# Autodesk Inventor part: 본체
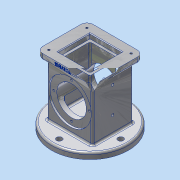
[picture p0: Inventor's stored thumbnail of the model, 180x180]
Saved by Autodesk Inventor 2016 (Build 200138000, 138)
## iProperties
Created: 2018-10
Part Number: 본체
Material: 알루미늄 6061
Document SubType Name: Modeling
Designer: MIRAE
Density: 2.7 g/cm^3
Appearance: 알루미늄 - 평지
Mass: 984.574 g
Surface Area: 743.905 cm^2
Volume: 364.657 cm^3
Author: MIRAE
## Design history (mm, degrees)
sketch "스케치1"
  geometry: C1 r 62.5 at (0, 0); 1 further point
  constraints: 1 centre point, 1 coincident
  dimensions: "d0" = 125 diameter of C1
extrude "돌출1" new body sketch "스케치1" distance "d1" = 10; taper "d2" = 0 deg
sketch "스케치2"
  geometry: L1 (37, 33)-(-37, 33); L2 (-37, 33)-(-37, -33); L3 (-37, -33)-(37, -33); L4 (37, -33)-(37, 33); L5 (37, 33)-(-37, -33); L6 (-37, 33)-(37, -33); 1 further point
  constraints: 12 end point, 2 midpoint, 2 parallel, 1 horizontal, 1 perpendicular
  dimensions: "d3" = 74 distance of L1.start L1.end; "d4" = 66 distance of L3.end L1.start
extrude "돌출2" join sketch "스케치2" distance "d5" = 88; taper "d6" = 0 deg
sketch "스케치3"
  geometry: L1 (46, 41)-(-46, 41); L2 (-46, 41)-(-46, -41); L3 (-46, -41)-(46, -41); L4 (46, -41)-(46, 41); L5 (46, 41)-(-46, -41); L6 (-46, 41)-(46, -41); 1 further point
  constraints: 12 end point, 2 midpoint, 2 parallel, 1 horizontal, 1 perpendicular
  dimensions: "d7" = 92 distance of L1.start L1.end; "d8" = 82 distance of L3.end L1.start
extrude "돌출3" join sketch "스케치3" distance "d9" = 10; taper "d10" = 0 deg
sketch "스케치4"
  geometry: L1 (22, 22)-(-22, 22); L2 (-22, 22)-(-22, -22); L3 (-22, -22)-(22, -22); L4 (22, -22)-(22, 22); L5 (22, 22)-(-22, -22); L6 (-22, 22)-(22, -22); 1 further point
  constraints: 12 end point, 2 midpoint, 2 parallel, 1 horizontal, 1 perpendicular
  dimensions: "d11" = 44 distance of L2.end L3.end; "d12" = 44 distance of L3.end L1.start
extrude "돌출4" cut sketch "스케치4" distance "d13" = 82; taper "d14" = 0 deg
sketch "스케치5"
  geometry: L1 (26, 26)-(-26, 26); L2 (-26, 26)-(-26, -26); L3 (-26, -26)-(26, -26); L4 (26, -26)-(26, 26); L5 (26, 26)-(-26, -26); L6 (-26, 26)-(26, -26); 1 further point
  constraints: 12 end point, 2 midpoint, 2 parallel, 1 horizontal, 1 perpendicular
  dimensions: "d15" = 52 distance of L2.end L3.end; "d16" = 52 distance of L3.end L1.start
extrude "돌출5" cut sketch "스케치5" distance "d17" = 8; taper "d18" = 0 deg
sketch "스케치6"
  geometry: L1 (-25.5, -10)-(99.5, -10) reference; C1 r 24 at (37, 44); 1 further point
  constraints: 1 centre point, 1 vertical alignment
  dimensions: "d19" = 48 diameter of C1; "d20" = 54 distance from line of L1 C1.centre
extrude "돌출6" cut sketch "스케치6" stored distance "d21" = 8; taper "d22" = 0 deg
sketch "스케치7"
  geometry: C1 r 24 at (37, 44) reference; C2 r 35 at (37, 44); 1 further point
  constraints: 1 centre point, 1 coincident
  dimensions: "d23" = 70 diameter of C2
extrude "돌출7" cut sketch "스케치7" distance "d24" = 3; taper "d25" = 0 deg
sketch "스케치8"
  geometry: L1 (15, -16)-(59, -16) reference; C1 r 24 at (37, -44) reference; C2 r 35 at (37, -44); 1 further point
  constraints: 1 centre point, 1 coincident
  dimensions: "d26" = 70 diameter of C2
extrude "돌출8" cut sketch "스케치8" distance "d27" = 3; taper "d28" = 0 deg
sketch "스케치9"
  geometry: 2 further points
  constraints: 1 vertical alignment
  dimensions: "d29" = 50 distance of point (0, 0) point (0, 50)
hole "구멍1" sketch "스케치9" at (0, 50) diameter "d30" = 9; stored, may be unused: countersink angle "d34" = 90 deg, drill point angle "d36" = 118 deg; dims "d31" = 6, "d32" = 4, "d33" = 2, "d35" = 8
sketch "스케치10"
  geometry: C1 r 24 at (0, 0) reference; 2 further points
  constraints: 1 vertical alignment
  dimensions: "d40" = 29 distance of C1.centre point (0, 29)
hole "구멍2" sketch "스케치10" at (0, 29) diameter "d41" = 3.242; stored, may be unused: countersink angle "d45" = 90 deg, drill point angle "d47" = 118 deg; dims "d42" = 4, "d43" = 4, "d44" = 2, "d46" = 6
sketch "스케치11"
  geometry: L1 (10, -29.5)-(10, 95.5) reference; 2 further points
  constraints: 1 horizontal alignment
  dimensions: "d51" = 37 distance from line of point (-27, 33) L1
hole "구멍3" sketch "스케치11" at (-27, 33) diameter "d53" = 4.134; stored, may be unused: countersink angle "d57" = 90 deg, drill point angle "d59" = 118 deg; dims "d54" = 10, "d55" = 4, "d56" = 2, "d58" = 14.2
sketch "스케치12"
  geometry: L1 (10, -29.5)-(10, 95.5) reference; 2 further points
  constraints: 1 horizontal alignment
  dimensions: "d60" = 80 distance from line of point (-70, 33) L1
hole "구멍4" sketch "스케치12" at (-70, 33) diameter "d61" = 4.134; stored, may be unused: countersink angle "d65" = 90 deg, drill point angle "d67" = 118 deg; dims "d62" = 10, "d63" = 4, "d64" = 2, "d66" = 14.2
sketch "스케치14"
  geometry: L1 (0, 10)-(92, 10) reference; L2 (0, 0)-(0, 10) reference; 2 further points
  constraints: 1 other
  dimensions: "d68" = 4 distance from line of L1 point (46, 6); "d69" = 46 distance from line of L2 point (46, 6)
feature "엠보싱1" sketch "스케치14" dims "d0" = 125, "d70" = 0.5, "d71" = 0
sketch "스케치15"
  geometry: L1 (0, 29.96)-(0, -17.464); L2 (-62.5, 0)-(62.5, 0) reference; L3 (-28, 0)-(-24.826, 18); L4 (-24.826, 18)-(0, 18); L5 (-28, 0)-(0, 0); L6 (0, 18)-(0, 0)
  constraints: 10 end point, 2 collinear, 2 point on line, 1 horizontal, 1 vertical, 1 vertical alignment
  dimensions: "d72" = 80 deg angle of L2 L3; "d74" = 18 distance between parallel lines of L2 L4; "d75" = 56 diameter of L3.start L1
revolve "회전1" sketch "스케치15" stored, may be unused: angle "d76" = 90 deg
fillet "모깎기1" dims "d77" = 3
fillet "모깎기2" dims "d78" = 3
fillet "모깎기3" dims "d79" = 3
chamfer "모따기1" distance "d80" = 1; stored, may be unused: second distance "d81" = 2, angle "d82" = 45 deg
fillet "모깎기4" dims "d83" = 3
fillet "모깎기5" dims "d84" = 3
fillet "모깎기6" dims "d85" = 10
fillet "모깎기7" dims "d86" = 3
fillet "모깎기8" dims "d87" = 3
hole "구멍5" diameter "d90" = 3.242; stored, may be unused: countersink angle "d94" = 90 deg, drill point angle "d96" = 118 deg; dims "d88" = 10, "d89" = 10, "d91" = 4, "d92" = 4, "d93" = 2, "d95" = 6
hole "구멍6" diameter "d99" = 3.242; stored, may be unused: countersink angle "d103" = 90 deg, drill point angle "d105" = 118 deg; dims "d97" = 10, "d98" = 10, "d100" = 4, "d101" = 4, "d102" = 2, "d104" = 6
hole "구멍7" diameter "d108" = 3.242; stored, may be unused: countersink angle "d112" = 90 deg, drill point angle "d114" = 118 deg; dims "d106" = 10, "d107" = 10, "d109" = 4, "d110" = 4, "d111" = 2, "d113" = 6
hole "구멍8" diameter "d117" = 3.242; stored, may be unused: countersink angle "d121" = 90 deg, drill point angle "d123" = 118 deg; dims "d115" = 10, "d116" = 10, "d118" = 4, "d119" = 4, "d120" = 2, "d122" = 6
sketch "스케치16"
  geometry: L1 (0, 0)-(60.595, 0); L2 (60.595, 0)-(60.595, 76.557); L3 (60.595, 76.557)-(0, 76.557); L4 (0, 76.557)-(0, 0); 1 further point
  constraints: 8 end point, 2 parallel, 1 horizontal, 1 perpendicular
extrude "돌출9" cut sketch "스케치16" stored distance "d124" = 10; taper "d125" = 0 deg
node "솔리드1"
pattern_circular "원형 패턴1" dims angle "d38" = 360 deg
pattern_circular "원형 패턴2" dims angle "d49" = 360 deg
mirror "대칭1"
